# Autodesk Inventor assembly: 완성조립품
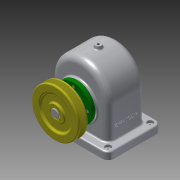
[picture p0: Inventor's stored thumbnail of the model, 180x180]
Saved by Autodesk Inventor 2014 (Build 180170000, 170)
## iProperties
Created: 2016-10
Part Number: 완성조립품
Document SubType Name: Assembly
Designer: a
Author: a
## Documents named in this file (15)
- C:\Users\a\Desktop\461008V1017\완성조립품.iam
- C:\Users\a\Desktop\461008V1017\본체.ipt
- C:\Users\a\Desktop\461008V1017\축.ipt
- C:\Users\a\Desktop\461008V1017\뒤커버.ipt
- C:\Users\a\Desktop\461008V1017\앞커버.ipt
- C:\Users\a\Desktop\461008V1017\베어링 6203.ipt
- C:\Users\a\Desktop\461008V1017\스퍼기어.ipt
- C:\Users\a\Desktop\461008V1017\V-벨트풀리.ipt
- C:\Users\a\Desktop\461008V1017\멈춤나사 - M4x10.ipt
- C:\Users\a\Desktop\461008V1017\오일씰 28 40 8.ipt
- C:\Users\a\Desktop\461008V1017\부시.ipt
- C:\Users\a\Desktop\461008V1017\키 - 6 x 6 x 22.ipt
- C:\Users\a\Desktop\461008V1017\키 - 5 x 5 x 18.ipt
- C:\Users\a\Desktop\461008V1017\볼트 M3 x 10.ipt
- C:\Users\a\Desktop\461008V1017\볼트 M3 x 8.ipt
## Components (9 placed, 3 different names)
1. V-벨트풀리:1
2. ISO 4762 M3 x 10:1
3. ISO 4762 M3 x 10:2
4. ISO 4762 M3 x 10:3
5. ISO 4762 M3 x 10:4
6. ISO 4762 M3 x 8:1
7. ISO 4762 M3 x 8:2
8. ISO 4762 M3 x 8:3
9. ISO 4762 M3 x 8:4
